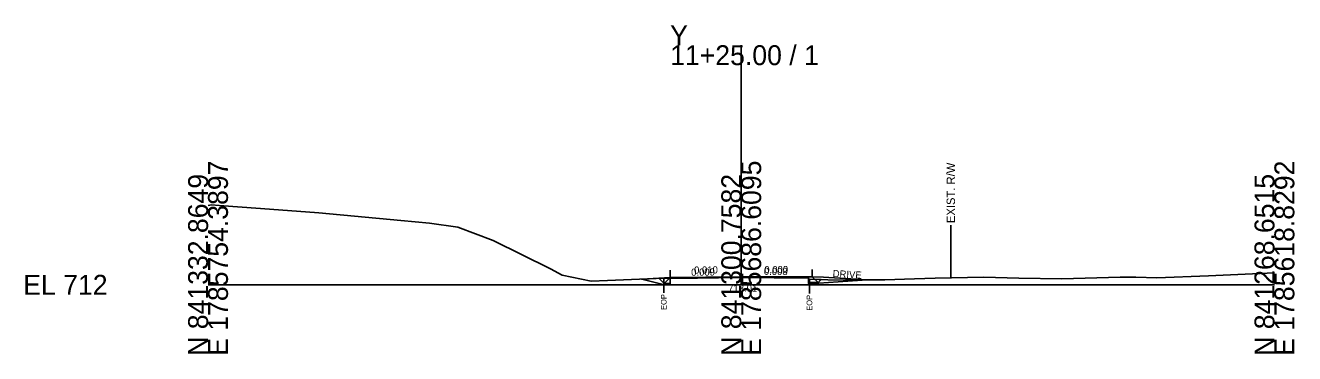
# Model space of a CAD drawing. Extents: x -26 to 153, y 990 to 3546.
# Drawn here: x -25.7 to 152.8, y 2490.3 to 2536.5 of the extents above; entities that cross this region are included whole.
import ezdxf

# ---------------------------------------------------------------- set-up
doc = ezdxf.new("R2010")
doc.units = 0
for name, color, linetype in [('Exist Cross Section Cell', 7, 'Continuous'), ('Exist XS Center Line Elevation Label', 7, 'Continuous'), ('Exist XS Ground Line', 7, 'Continuous'), ('Old_Level_10', 7, 'Continuous'), ('Prop XS Dump Level', 7, 'Continuous'), ('Prop XS Earthwork Shape', 7, 'Continuous'), ('Prop XS EOT Tick Mark', 7, 'Continuous'), ('Prop XS Finish Grade', 7, 'Continuous'), ('Prop XS Finish Grade Pavement', 7, 'Continuous'), ('Prop XS Pvmt Edge Slope', 7, 'Continuous'), ('Prop XS SE Text', 7, 'Continuous'), ('Prop XS Subgrade Earthwork', 7, 'Continuous'), ('Scratch_Level_1', 7, 'Continuous'), ('Scratch_Level_6', 7, 'Continuous')]:
    doc.layers.add(name, color=color, linetype=linetype)

msp = doc.modelspace()

# ---------------------------------------------------------------- linework, layer by layer
at = {"layer": 'Exist Cross Section Cell'}
for p, q in [((75, 2500), (75, 2533.72)), ((0, 2500), (75, 2500)), ((75, 2500), (150, 2500))]:
    msp.add_line(p, q, dxfattribs=at)
at = {"layer": 'Exist XS Ground Line'}
msp.add_lwpolyline([(0, 2511.18), (0.47, 2511.24), (1.55, 2511.18), (7.37, 2510.76), (15.57, 2510.15), (27.12, 2509.03), (31.14, 2508.68), (35.14, 2508.12), (40.12, 2506.25), (48.16, 2502.24), (49.82, 2501.34), (53.91, 2500.51), (56.18, 2500.6), (64.06, 2500.91), (68.84, 2500.94), (74.77, 2501.01), (80.41, 2500.97), (84.46, 2500.93), (84.6, 2500.78), (87.17, 2500.7), (90.19, 2500.63), (92.77, 2500.68), (95.22, 2500.72), (99.35, 2500.84), (102.3, 2500.95), (109.14, 2501.05), (114.05, 2500.94), (120.1, 2500.86), (128.31, 2501.05), (130.49, 2501.07), (133.44, 2500.97), (140.72, 2501.26), (150, 2501.66)], dxfattribs=at)
at = {"layer": 'Old_Level_10'}
for p, q in [((104.48, 2508.38), (104.48, 2500.98)), ((64.1, 2500.91), (64.1, 2498.86)), ((84.58, 2500.8), (84.58, 2498.75))]:
    msp.add_line(p, q, dxfattribs=at)
at = {"layer": 'Prop XS Earthwork Shape'}
for points in [[(64.01, 2500.05), (61, 2500.79), (64.06, 2500.91), (65, 2500.92), (65, 2500.12)], [(64.06, 2500.91), (65, 2500.92), (65, 2500.21), (64.16, 2500.2), (63.47, 2500.89)], [(84.46, 2500.93), (84.46, 2500.22), (85.92, 2500.22), (92.72, 2500.68), (90.19, 2500.63), (87.17, 2500.7), (84.6, 2500.78)], [(84.58, 2500.8), (84.6, 2500.78), (86.25, 2500.73), (85.83, 2500.31), (85, 2500.31), (84.58, 2500.31)]]:
    msp.add_lwpolyline(points, close=True, dxfattribs=at)
at = {"layer": 'Prop XS EOT Tick Mark'}
for p, q in [((65, 2501.04), (65, 2502.04)), ((85, 2501.14), (85, 2502.14))]:
    msp.add_line(p, q, dxfattribs=at)
at = {"layer": 'Prop XS Finish Grade'}
for p, q in [((63.43, 2500.93), (61, 2500.79)), ((65, 2501.04), (63.43, 2500.93)), ((85, 2501.14), (86.57, 2501.05)), ((86.57, 2501.05), (92.72, 2500.68))]:
    msp.add_line(p, q, dxfattribs=at)
at = {"layer": 'Prop XS Finish Grade Pavement'}
for p, q in [((65, 2501.04), (75, 2501.14)), ((75, 2501.14), (85, 2501.14))]:
    msp.add_line(p, q, dxfattribs=at)
at = {"layer": 'Prop XS Pvmt Edge Slope'}
for p, q in [((65, 2501.04), (64.01, 2500.05)), ((85, 2501.14), (85.92, 2500.22))]:
    msp.add_line(p, q, dxfattribs=at)
at = {"layer": 'Prop XS Subgrade Earthwork'}
for p, q in [((64.01, 2500.05), (61, 2500.79)), ((65, 2500.12), (64.01, 2500.05)), ((65, 2500.12), (65, 2500.92)), ((84.46, 2500.93), (84.46, 2500.22)), ((84.46, 2500.22), (85.92, 2500.22)), ((85.92, 2500.22), (92.72, 2500.68))]:
    msp.add_line(p, q, dxfattribs=at)
at = {"layer": 'Scratch_Level_1'}
for p, q in [((64.06, 2500.91), (74.77, 2501.01)), ((74.77, 2501.01), (84.46, 2500.93))]:
    msp.add_line(p, q, dxfattribs=at)
at = {"layer": 'Scratch_Level_6'}
for p, q in [((65, 2500.92), (75, 2501.01)), ((65, 2500.92), (65, 2501)), ((70.24, 2500.97), (65, 2500.92)), ((75, 2501.01), (70.24, 2500.97)), ((70.24, 2500.97), (74.77, 2501.01)), ((74.77, 2501.01), (70.24, 2500.97)), ((75, 2501.01), (84.46, 2501.01)), ((84.46, 2501.01), (75, 2501.01)), ((84.46, 2500.93), (84.46, 2501.19)), ((84.46, 2500.93), (84.46, 2501.01))]:
    msp.add_line(p, q, dxfattribs=at)
for points in [[(65, 2500.92), (68.84, 2500.94), (74.77, 2501.01)], [(74.77, 2501.01), (80.41, 2500.97), (84.46, 2500.93)]]:
    msp.add_lwpolyline(points, dxfattribs=at)

# ---------------------------------------------------------------- texts
at = {"layer": 'Exist Cross Section Cell'}
for s, p in [('Y', (65, 2533.72)), ('11+25.00 / 1', (65, 2530.92)), ('EL 712', (-26, 2498.6))]:
    msp.add_text(s, height=2.8, dxfattribs=at).set_placement(p)
for s, p in [('E 1785686.6095', (77.8, 2490)), ('E 1785754.3897', (2.8, 2490)), ('E 1785618.8292', (152.8, 2490)), ('N 841332.8649', (0, 2490)), ('N 841300.7582', (75, 2490)), ('N 841268.6515', (150, 2490))]:
    msp.add_text(s, height=2.8, rotation=90, dxfattribs=at).set_placement(p)
at = {"layer": 'Exist XS Center Line Elevation Label'}
msp.add_text('713.01', height=1, dxfattribs=at).set_placement((73.16, 2499.01))
at = {"layer": 'Old_Level_10'}
for s, height, p in [('EXIST. R/W', 1.181, (105.07, 2508.68)), ('EOP', 0.787, (64.49, 2496.46)), ('EOP', 0.787, (84.98, 2496.35))]:
    msp.add_text(s, height=height, rotation=90, dxfattribs=at).set_placement(p)
at = {"layer": 'Prop XS Dump Level'}
msp.add_text('DRIVE', height=1, rotation=356.5664, dxfattribs=at).set_placement((87.84, 2501.1))
at = {"layer": 'Prop XS SE Text'}
msp.add_text('0.010', height=1, rotation=0.5729, dxfattribs=at).set_placement((68.37, 2501.57))
msp.add_text('0.000', height=1, dxfattribs=at).set_placement((78.25, 2501.64))
at = {"layer": 'Scratch_Level_1'}
for s, rotation, p in [('0.009', 0.5389, (67.96, 2501.27)), ('0.008', 359.5531, (78.18, 2501.4))]:
    msp.add_text(s, height=1, rotation=rotation, dxfattribs=at).set_placement(p)

doc.saveas('drawing.dxf')
